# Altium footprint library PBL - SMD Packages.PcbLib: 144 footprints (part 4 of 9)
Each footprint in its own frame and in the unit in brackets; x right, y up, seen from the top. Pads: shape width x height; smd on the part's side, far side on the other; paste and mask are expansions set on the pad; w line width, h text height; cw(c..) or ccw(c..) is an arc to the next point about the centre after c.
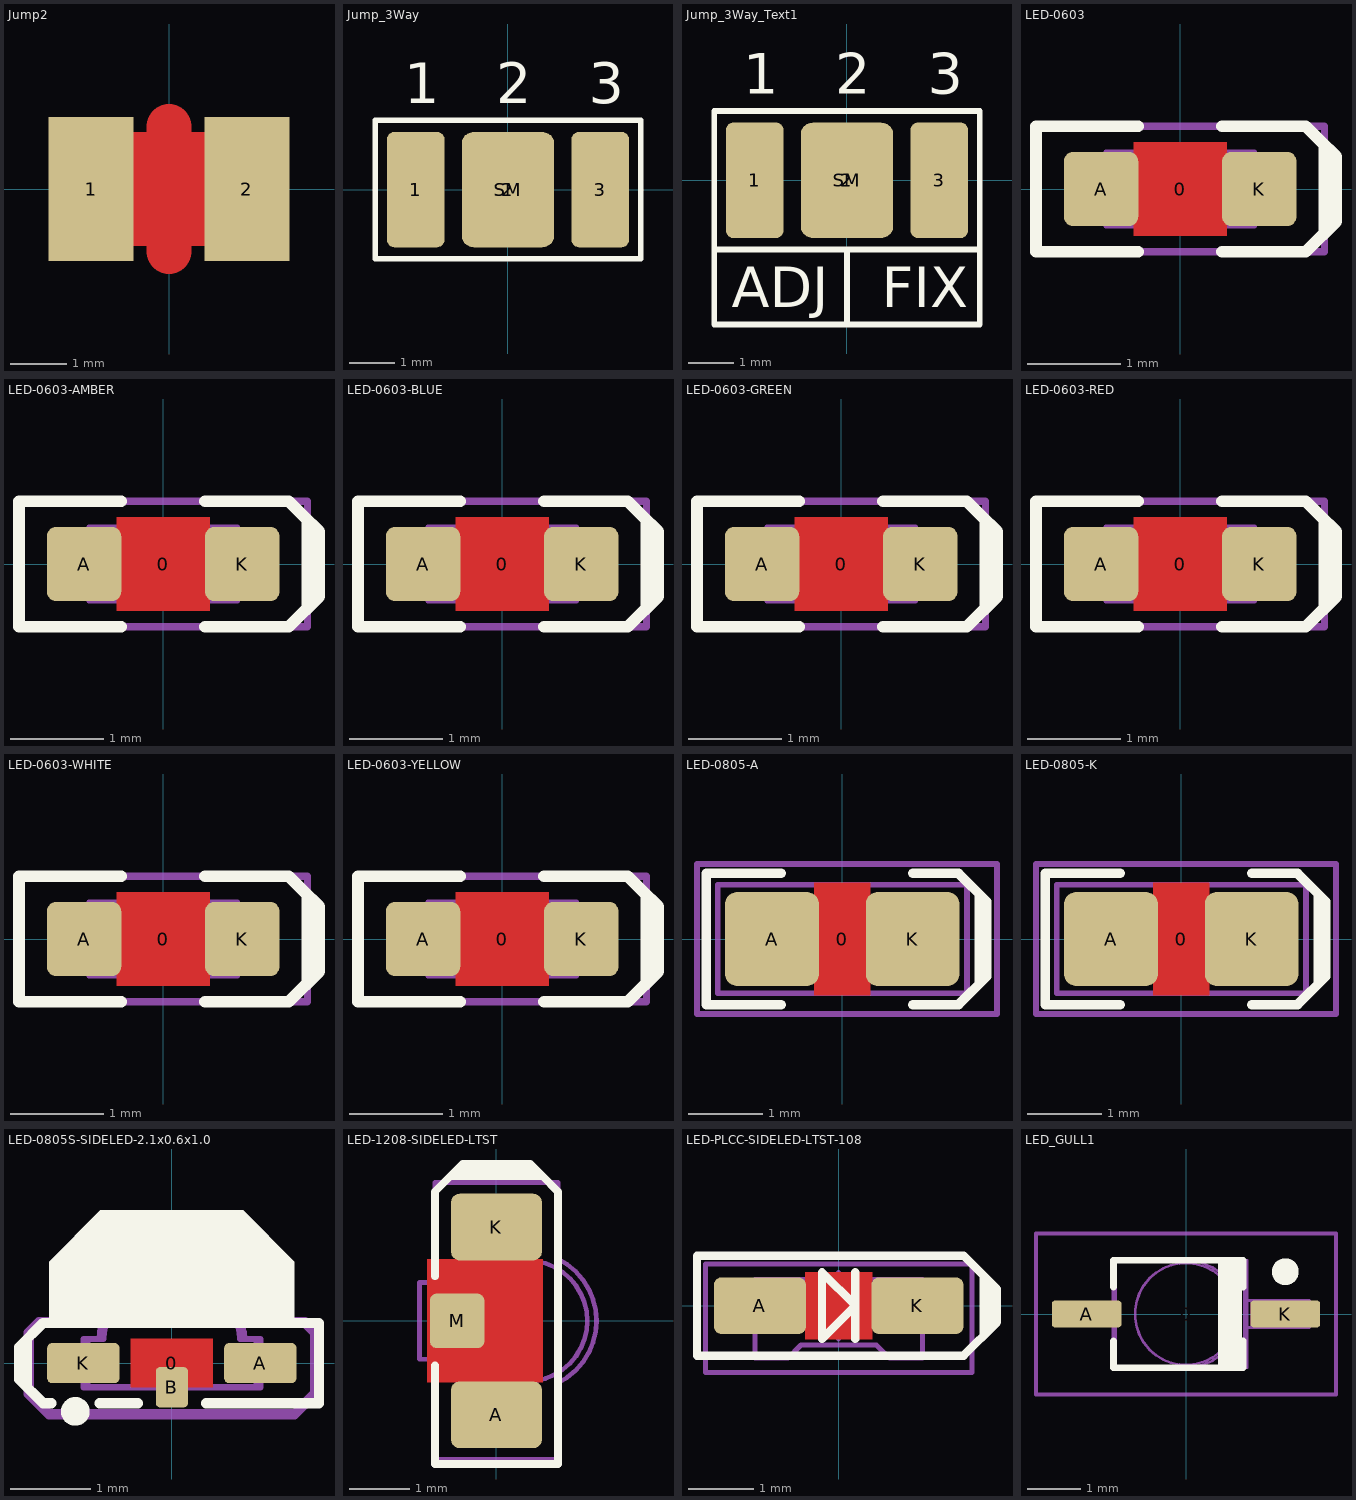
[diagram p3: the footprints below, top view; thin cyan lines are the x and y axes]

## Jump2 [mm] "SMT Battery jumper pads"
pads (2):
  rrect1% 1.5x2.54 smd paste-2: 1(-1.373,0) 2(1.373,0)
Top Layer:
  lines w0.8: 0,-1.1 0,1.1
  lines w1: -1,-0.5 1,-0.5 ; -1,0.5 1,0.5
Top Overlay:
  lines w0.127: -0.8,-1.1 -0.8,1.1 ; 0.8,-1.1 0.8,1.1

## Jump_3Way [mil] "SMT Battery jumper pads"
pads (4):
  rrect25% 50x100 smd: 1(-80,0) 3(80,0)
  rrect25% 80x100 smd: 2(0,0)
  rrect25% 218x108 on Top Solder: SM(0,0)
Top Overlay:
  lines w5: -115,-60 -115,60 115,60 115,-60 -115,-60
  text "1" at -90,75 h35
  text "2" at -10,75 h35
  text "3" at 70,75 h35
13 - 3D Top Side:
  lines w3: -115,-60 -115,60 115,60 115,-60 -115,-60

## Jump_3Way_Text1 [mil] "SMT jumper for fixed or variable"
pads (4):
  rrect25% 50x100 smd: 1(-80,0) 3(80,0)
  rrect25% 80x100 smd: 2(0,0)
  rrect25% 218x108 on Top Solder: SM(0,0)
Top Overlay:
  lines w5: 0,-125 0,-60 ; -115,-60 -115,-125 115,-125 115,-60 ; -115,-60 -115,60 115,60 115,-60 ; -115,-60 115,-60
  text "FIX" at 30,-110 h35
  text "ADJ" at -100,-110 h35
  text "1" at -90,75 h35
  text "2" at -10,75 h35
  text "3" at 70,75 h35
13 - 3D Top Side:
  lines w3: -115,-60 -115,60 115,60 115,-60 -115,-60

## LED-0603 [mm]
height 0.8
pads (3):
  round 0.254 on Mech15: 0(0,0)
  rrect25% 0.8x0.8 smd: A(-0.85,0) K(0.85,0)
Top Layer:
  pour cut-out: -0.5,0.5 0.5,0.5 0.5,-0.5 -0.5,-0.5
Top Overlay:
  lines w0.127: -0.45,-0.675 -1.55,-0.675 -1.55,0.675 -0.45,0.675 ; 0.45,-0.675 1.35,-0.675 1.55,-0.475 1.55,0.475 1.35,0.675 0.45,0.675 ; 1.5,0.525 1.675,0.35 1.675,-0.35 1.525,-0.5
08 - Top ASM Des:
  text ".Designator" at -1.325,-0.3 h1
13 - 3D Top Side:
  lines w0.05: -0.6,-0.4 -0.6,0.399 0.6,0.4 0.6,-0.4 -0.6,-0.399 ; -0.505,-0.398 -0.505,0.398 ; -0.5,-0.4 -0.8,-0.4 -0.8,0.4 -0.5,0.4 ; 0.5,-0.4 0.8,-0.4 0.8,0.4 0.5,0.4 ; 0.505,-0.398 0.505,0.398 ; -0.599,-0.398 0.599,-0.398 0.599,0.398 -0.599,0.398 -0.599,-0.398
15 - Top Courtyards:
  lines w0.076: -1.55,-0.675 1.55,-0.675 1.55,0.675 -1.55,0.675 -1.55,-0.675
3D body "LED 0603 APT1608 GREEN.STEP": height 0.75, standoff 0, extent -0.8,-0.4 0.8,0.4

## LED-0603-AMBER [mm]
height 0.8
pads (3):
  round 0.254 on Mech15: 0(0,0)
  rrect25% 0.8x0.8 smd: A(-0.85,0) K(0.85,0)
Top Layer:
  pour cut-out: -0.5,0.5 0.5,0.5 0.5,-0.5 -0.5,-0.5
Top Overlay:
  lines w0.127: -0.45,-0.675 -1.55,-0.675 -1.55,0.675 -0.45,0.675 ; 0.45,-0.675 1.35,-0.675 1.55,-0.475 1.55,0.475 1.35,0.675 0.45,0.675 ; 1.5,0.525 1.675,0.35 1.675,-0.35 1.525,-0.5
08 - Top ASM Des:
  text ".Designator" at -1.325,-0.3 h1
13 - 3D Top Side:
  lines w0.05: -0.6,-0.4 -0.6,0.399 0.6,0.4 0.6,-0.4 -0.6,-0.399 ; -0.505,-0.398 -0.505,0.398 ; -0.5,-0.4 -0.8,-0.4 -0.8,0.4 -0.5,0.4 ; 0.5,-0.4 0.8,-0.4 0.8,0.4 0.5,0.4 ; 0.505,-0.398 0.505,0.398 ; -0.599,-0.398 0.599,-0.398 0.599,0.398 -0.599,0.398 -0.599,-0.398
15 - Top Courtyards:
  lines w0.076: -1.55,-0.675 -1.55,0.675 1.55,0.675 1.55,-0.675 -1.55,-0.675
3D body "LED 0603 APT1608 AMBER.STEP": height 0.75, standoff 0, extent -0.8,-0.4 0.8,0.4

## LED-0603-BLUE [mm]
height 0.8
pads (3):
  round 0.254 on Mech15: 0(0,0)
  rrect25% 0.8x0.8 smd: A(-0.85,0) K(0.85,0)
Top Layer:
  pour cut-out: -0.5,0.5 0.5,0.5 0.5,-0.5 -0.5,-0.5
Top Overlay:
  lines w0.127: -0.45,-0.675 -1.55,-0.675 -1.55,0.675 -0.45,0.675 ; 0.45,-0.675 1.35,-0.675 1.55,-0.475 1.55,0.475 1.35,0.675 0.45,0.675 ; 1.5,0.525 1.675,0.35 1.675,-0.35 1.525,-0.5
08 - Top ASM Des:
  text ".Designator" at -1.425,-0.3 h1
13 - 3D Top Side:
  lines w0.05: -0.6,-0.4 -0.6,0.399 0.6,0.4 0.6,-0.4 -0.6,-0.399 ; -0.505,-0.398 -0.505,0.398 ; -0.5,-0.4 -0.8,-0.4 -0.8,0.4 -0.5,0.4 ; 0.5,-0.4 0.8,-0.4 0.8,0.4 0.5,0.4 ; 0.505,-0.398 0.505,0.398 ; -0.599,-0.398 0.599,-0.398 0.599,0.398 -0.599,0.398 -0.599,-0.398
15 - Top Courtyards:
  lines w0.076: -1.55,-0.675 1.55,-0.675 1.55,0.675 -1.55,0.675 -1.55,-0.675
3D body "LED 0603 APT1608 BLUE.STEP": height 0.75, standoff 0, extent -0.8,-0.4 0.8,0.4

## LED-0603-GREEN [mm]
height 0.8
pads (3):
  round 0.254 on Mech15: 0(0,0)
  rrect25% 0.8x0.8 smd: A(-0.85,0) K(0.85,0)
Top Layer:
  pour cut-out: -0.5,0.5 0.5,0.5 0.5,-0.5 -0.5,-0.5
Top Overlay:
  lines w0.127: -0.45,-0.675 -1.55,-0.675 -1.55,0.675 -0.45,0.675 ; 0.45,-0.675 1.35,-0.675 1.55,-0.475 1.55,0.475 1.35,0.675 0.45,0.675 ; 1.5,0.525 1.675,0.35 1.675,-0.35 1.525,-0.5
08 - Top ASM Des:
  text ".Designator" at -1.4,-0.275 h1
13 - 3D Top Side:
  lines w0.05: -0.6,-0.4 -0.6,0.399 0.6,0.4 0.6,-0.4 -0.6,-0.399 ; -0.505,-0.398 -0.505,0.398 ; -0.5,-0.4 -0.8,-0.4 -0.8,0.4 -0.5,0.4 ; 0.5,-0.4 0.8,-0.4 0.8,0.4 0.5,0.4 ; 0.505,-0.398 0.505,0.398 ; -0.599,-0.398 0.599,-0.398 0.599,0.398 -0.599,0.398 -0.599,-0.398
15 - Top Courtyards:
  lines w0.076: -1.55,-0.675 -1.55,0.675 1.55,0.675 1.55,-0.675 -1.55,-0.675
3D body "LED 0603 APT1608 GREEN.STEP": height 0.75, standoff 0, extent -0.8,-0.4 0.8,0.4

## LED-0603-RED [mm]
height 0.8
pads (3):
  round 0.254 on Mech15: 0(0,0)
  rrect25% 0.8x0.8 smd: A(-0.85,0) K(0.85,0)
Top Layer:
  pour cut-out: -0.5,0.5 0.5,0.5 0.5,-0.5 -0.5,-0.5
Top Overlay:
  lines w0.127: -0.45,-0.675 -1.55,-0.675 -1.55,0.675 -0.45,0.675 ; 0.45,-0.675 1.35,-0.675 1.55,-0.475 1.55,0.475 1.35,0.675 0.45,0.675 ; 1.5,0.525 1.675,0.35 1.675,-0.35 1.525,-0.5
08 - Top ASM Des:
  text ".Designator" at -1.375,-0.25 h1
13 - 3D Top Side:
  lines w0.05: -0.6,-0.4 -0.6,0.399 0.6,0.4 0.6,-0.4 -0.6,-0.399 ; -0.505,-0.398 -0.505,0.398 ; -0.5,-0.4 -0.8,-0.4 -0.8,0.4 -0.5,0.4 ; 0.5,-0.4 0.8,-0.4 0.8,0.4 0.5,0.4 ; 0.505,-0.398 0.505,0.398 ; -0.599,-0.398 0.599,-0.398 0.599,0.398 -0.599,0.398 -0.599,-0.398
15 - Top Courtyards:
  lines w0.076: -1.55,-0.675 -1.55,0.675 1.55,0.675 1.55,-0.675 -1.55,-0.675
3D body "LED 0603 APT1608 RED.STEP": height 0.75, standoff 0, extent -0.8,-0.4 0.8,0.4

## LED-0603-WHITE [mm]
height 0.8
pads (3):
  round 0.254 on Mech15: 0(0,0)
  rrect25% 0.8x0.8 smd: A(-0.85,0) K(0.85,0)
Top Layer:
  pour cut-out: -0.5,0.5 0.5,0.5 0.5,-0.5 -0.5,-0.5
Top Overlay:
  lines w0.127: -0.45,-0.675 -1.55,-0.675 -1.55,0.675 -0.45,0.675 ; 0.45,-0.675 1.35,-0.675 1.55,-0.475 1.55,0.475 1.35,0.675 0.45,0.675 ; 1.5,0.525 1.675,0.35 1.675,-0.35 1.525,-0.5
08 - Top ASM Des:
  text ".Designator" at -1.4,-0.3 h1
13 - 3D Top Side:
  lines w0.05: -0.6,-0.4 -0.6,0.399 0.6,0.4 0.6,-0.4 -0.6,-0.399 ; -0.505,-0.398 -0.505,0.398 ; -0.5,-0.4 -0.8,-0.4 -0.8,0.4 -0.5,0.4 ; 0.5,-0.4 0.8,-0.4 0.8,0.4 0.5,0.4 ; 0.505,-0.398 0.505,0.398 ; -0.599,-0.398 0.599,-0.398 0.599,0.398 -0.599,0.398 -0.599,-0.398
15 - Top Courtyards:
  lines w0.076: -1.55,-0.675 -1.55,0.675 1.55,0.675 1.55,-0.675 -1.55,-0.675
3D body "LED 0603 APT1608 WHITE.STEP": height 0.75, standoff 0, extent -0.8,-0.4 0.8,0.4

## LED-0603-YELLOW [mm]
height 0.8
pads (3):
  round 0.254 on Mech15: 0(0,0)
  rrect25% 0.8x0.8 smd: A(-0.85,0) K(0.85,0)
Top Layer:
  pour cut-out: -0.5,0.5 0.5,0.5 0.5,-0.5 -0.5,-0.5
Top Overlay:
  lines w0.127: -0.45,-0.675 -1.55,-0.675 -1.55,0.675 -0.45,0.675 ; 0.45,-0.675 1.35,-0.675 1.55,-0.475 1.55,0.475 1.35,0.675 0.45,0.675 ; 1.5,0.525 1.675,0.35 1.675,-0.35 1.525,-0.5
08 - Top ASM Des:
  text ".Designator" at -1.375,-0.25 h1
13 - 3D Top Side:
  lines w0.05: -0.6,-0.4 -0.6,0.399 0.6,0.4 0.6,-0.4 -0.6,-0.399 ; -0.505,-0.398 -0.505,0.398 ; -0.5,-0.4 -0.8,-0.4 -0.8,0.4 -0.5,0.4 ; 0.5,-0.4 0.8,-0.4 0.8,0.4 0.5,0.4 ; 0.505,-0.398 0.505,0.398 ; -0.599,-0.398 0.599,-0.398 0.599,0.398 -0.599,0.398 -0.599,-0.398
15 - Top Courtyards:
  lines w0.076: -1.55,-0.675 1.55,-0.675 1.55,0.675 -1.55,0.675 -1.55,-0.675
3D body "LED 0603 APT1608 YELLOW.STEP": height 0.75, standoff 0, extent -0.8,-0.4 0.8,0.4

## LED-0805-A [mil]
height 31.5
pads (3):
  round 20 on Mech15: 0(0,0)
  rrect25% 50x50 smd: A(-37.5,0) K(37.5,0)
Top Layer:
  pour cut-out: -15,30 15,30 15,-30 -15,-30
Top Overlay:
  lines w5: -32.5,-35 -72.5,-35 -72.5,35 -32.5,35 ; 37.5,-35 62,-35 77,-20 77,20 62,35 37.5,35 ; 73,-24 73,24
08 - Top ASM Des:
  text ".Designator" at -62.99,-10.83 h39.37
13 - 3D Top Side:
  lines w3: -66.5,-29 -66.5,29 66.5,29 66.5,-29 -66.5,-29
15 - Top Courtyards:
  lines w3: -77.5,-40 -77.5,40 82.5,40 82.5,-40 -77.5,-40
3D body: height 3.94, standoff 0, extent -11.81,-15.75 11.81,15.75
3D body: height 3.94, standoff 0, extent -39.37,-24.61 39.37,24.61
3D body: height 11.81, standoff 3.94, extent -39.37,-24.61 39.37,24.61
3D body: height 31.5, standoff 11.81, extent -26.49,-24.61 28.65,24.6

## LED-0805-K [mil]
height 31.5
pads (3):
  round 20 on Mech15: 0(0,0)
  rrect25% 50x50 smd: A(-37.5,0) K(37.5,0)
Top Layer:
  pour cut-out: -15,30 15,30 15,-30 -15,-30
Top Overlay:
  lines w5: -32.5,-35 -72.5,-35 -72.5,35 -32.5,35 ; 37.5,-35 62,-35 77,-20 77,20 62,35 37.5,35 ; 73,-24 73,24
08 - Top ASM Des:
  text ".Designator" at -64.96,-10.83 h39.37
13 - 3D Top Side:
  lines w3: -66.5,-29 -66.5,29 66.5,29 66.5,-29 -66.5,-29
15 - Top Courtyards:
  lines w3: -77.5,-40 -77.5,40 82.5,40 82.5,-40 -77.5,-40
3D body: height 3.94, standoff 0, extent -11.81,-15.75 11.81,15.75
3D body: height 3.94, standoff 0, extent -39.37,-24.61 39.37,24.61
3D body: height 11.81, standoff 3.94, extent -39.37,-24.61 39.37,24.61
3D body: height 31.5, standoff 11.81, extent -28.65,-24.6 26.49,24.61

## LED-0805S-SIDELED-2.1x0.6x1.0 [mm] "Lite-On Inc PLCC Side LED"
height 0.8
pads (4):
  round 0.508 on Mech15: 0(0,0)
  rrect25% 0.9x0.5 smd: A(1.1,0) K(-1.1,0)
  rrect25% 0.4x0.5 smd: B(0,-0.3)
Top Layer:
  pour cut-out: -0.508,0.3 0.508,0.3 0.508,-0.3 -0.508,-0.3
Top Overlay:
  circle w0.203: c-1.2,-0.6 r0.076
  region: -1.524,0.5 1.524,0.5 1.524,1.262 0.889,1.897 -0.889,1.897 -1.524,1.262
  lines w0.127: -1.8,-0.3 -1.8,0.3 ; -1.5,-0.5 -1.6,-0.5 -1.9,-0.2 -1.9,0.2 -1.6,0.5 1.829,0.5 1.829,-0.5 0.425,-0.5 ; -0.9,-0.5 -0.425,-0.5
13 - 3D Top Side:
  lines w0.076: -1.05,-0.3 1.05,-0.3 1.05,0.3 0.85,0.3 ccw(c0.3,0.3) 0.3,0.85 -0.3,0.85 ccw(c-0.3,0.3) -0.85,0.3 -1.05,0.3 -1.05,-0.3
15 - Top Courtyards:
  lines w0.076: -1.1,-0.3 -1.1,0.3 -0.9,0.3 cw(c-0.35,0.3) -0.35,0.85 0.35,0.85 cw(c0.35,0.3) 0.9,0.3 1.1,0.3 1.1,-0.3 -1.1,-0.3
  lines w0.127: -1.778,-0.381 -1.524,-0.635 1.524,-0.635 1.778,-0.381 1.778,0.381 1.651,0.508 1.27,0.508 0.762,1.016 -0.762,1.016 -1.27,0.508 -1.651,0.508 -1.778,0.381 -1.778,-0.381
3D body "LED_SIDELED-2.1x0.6x1.0 WHITE maxtol.STEP": height 0.7, standoff 0, extent -1.1,-0.3 1.1,0.8

## LED-1208-SIDELED-LTST [mm] "Lite-On Inc 1208 SMD Side LED"
height 1
pads (3):
  rrect25% 1.5x1.1 smd: A(0,-1.55) K(0,1.55)
  rrect25% 0.9x0.9 smd: M(-0.65,0)
Top Layer:
  pour cut-out: -1.143,1.016 0.762,1.016 0.762,-1.016 -1.143,-1.016
Top Overlay:
  lines w0.127: -1.016,-0.737 -1.016,-2.362 1.016,-2.362 1.016,2.134 0.762,2.388 ; -1.016,0.737 -1.016,2.134 -0.762,2.388 ; -0.686,2.464 -0.559,2.591 0.559,2.591 0.66,2.489 ; -0.762,2.388 -0.66,2.489 0.66,2.489 ; -0.762,2.388 0.762,2.388 ; 0.66,2.489 0.762,2.388
13 - 3D Top Side:
  lines w0.076: -0.5,-1.5 0.5,-1.5 0.5,-1 ccw(c0.5,0) 1.5,0 ccw(c0.5,0) 0.5,1 0.5,1.5 -0.5,1.5 -0.5,-1.5
15 - Top Courtyards:
  lines w0.076: -0.508,0 0.508,0 ; 0,-0.508 0,0.508 ; 1.009,-1.027 ccw(c0.508,0) 1.009,1.027 ; 1.016,-1.023 1.016,-2.286 -1.016,-2.286 -1.016,-0.635 -1.27,-0.635 -1.27,0.635 -1.016,0.635 -1.016,2.286 1.016,2.286 1.016,1.023
3D body: height 1, standoff 0, extent 0.5,-1 1.5,1
3D body: height 1, standoff 0, extent -0.5,-1.5 0.5,1.5

## LED-PLCC-SIDELED-LTST-108 [mm] "Lite-On Inc PLCC Side LED"
height 0.8
pads (2):
  rrect25% 1.4x0.86 smd: A(-1.2,0) K(1.2,0)
Top Layer:
  pour cut-out: -0.508,0.508 0.508,0.508 0.508,-0.508 -0.508,-0.508
Top Overlay:
  lines w0.127: 0.254,-0.508 0.254,0.508 ; 2.21,-0.457 2.21,0.457 ; 2.311,-0.356 2.311,0.356 ; -2.159,-0.762 1.905,-0.762 2.413,-0.254 2.413,0.254 1.905,0.762 -2.159,0.762 -2.159,-0.762 ; -0.254,-0.508 -0.254,0.508 0.254,0 -0.254,-0.508
13 - 3D Top Side:
  lines w0.076: -1.275,-0.8 -1.275,0.4 1.275,0.4 1.275,-0.8 0.775,-0.8 0.575,-0.6 -0.575,-0.6 -0.775,-0.8 -1.275,-0.8
15 - Top Courtyards:
  lines w0.076: -0.508,0 0.508,0 ; 0,-0.508 0,0.508 ; -2.032,-1.016 2.032,-1.016 2.032,0.635 -2.032,0.635 -2.032,-1.016
3D body: height 0.15, standoff 0, extent 0.725,-0.3 1.425,0.3
3D body: height 0.15, standoff 0, extent -1.425,-0.3 -0.725,0.3
3D body: height 0.8, standoff 0, extent -1.275,-0.8 1.275,0.4

## LED_GULL1 [mm]
pads (3):
  round 0.508 on Mech15: 0(0,0)
  rrect25% 1.3x0.5 smd: A(-1.85,0) K(1.85,0)
Top Overlay:
  circle w0.4: c1.85,0.788 r0.05
  rectangle: 0.6,-1 1.041,1
  lines w0.127: -1.35,-0.5 -1.35,-1 1.067,-1 1.067,-0.5 ; -1.35,0.5 -1.35,1 1.067,1 1.067,0.5
13 - 3D Top Side:
  circle w0.05: c0,0 r0.95
  lines w0.05: -1.9,-0.2 -1.9,0.2 ; -1.77,-0.2 -1.77,0.2 ; -1.499,-0.2 -1.499,0.2 ; -1.36,-0.2 -2.3,-0.2 -2.3,0.2 -1.36,0.2 ; -1.31,-1 -1.31,1 ; -0.001,-1 ccw(c0,0) 0.001,1 ; 1.09,-1 1.09,1 ; 1.14,-0.25 2.3,-0.25 2.3,0.25 1.14,0.25 ; 1.23,-0.25 1.23,0.25 ; 1.499,-0.25 1.499,0.25 ; 1.77,-0.25 1.77,0.25 ; 1.9,-0.25 1.9,0.25 ; -1.36,-1 1.14,-1 1.14,1 -1.36,1 -1.36,-1
15 - Top Courtyards:
  lines w0.076: -2.794,-1.5 -2.794,1.5 2.794,1.5 2.794,-1.5 -2.794,-1.5
3D body "LED_GullWing.STEP": height 2.76, standoff 0, extent -2.3,-1 2.3,1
